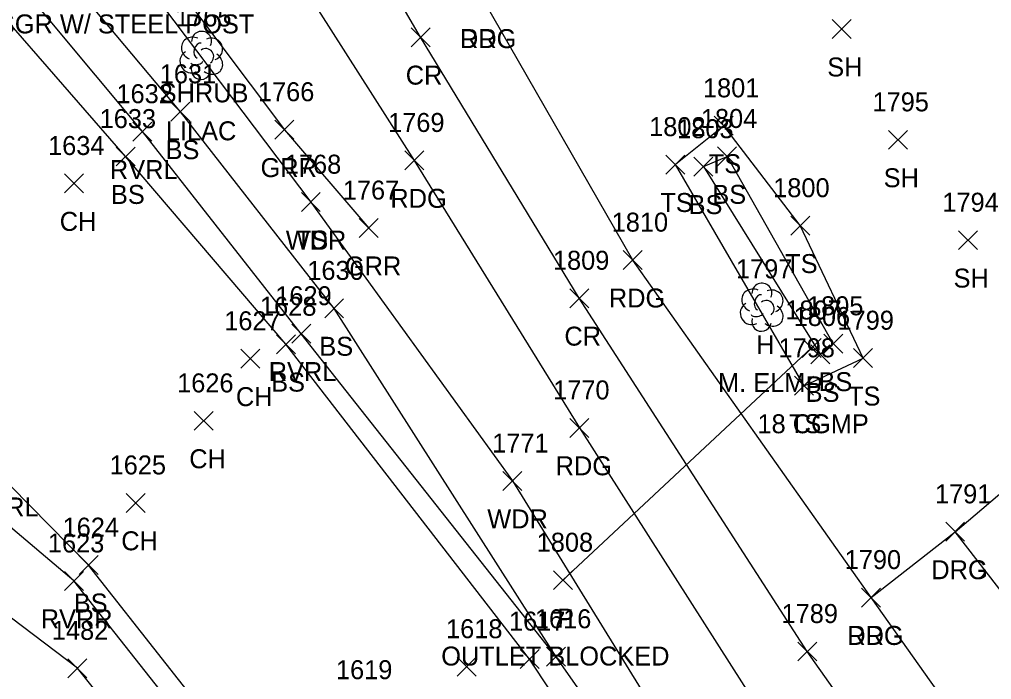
# Model space of a CAD drawing. Extents: x 1653908 to 1654393, y 539913 to 544256.
# Drawn here: x 1654097.1 to 1654199.7, y 541548 to 541617.6 of the extents above; entities that cross this region are included whole.
import ezdxf

# ---------------------------------------------------------------- set-up
doc = ezdxf.new("R2010")
doc.units = 0
for name, color, linetype in [('C_A', 7, 'Continuous'), ('D_A', 7, 'Continuous'), ('D_C', 7, 'Continuous'), ('D_I', 7, 'Continuous'), ('D_TIC', 7, 'Continuous'), ('DCP', 7, 'Continuous'), ('L_A', 7, 'Continuous'), ('L_C', 7, 'Continuous'), ('L_I', 7, 'Continuous'), ('L_TIC', 7, 'Continuous'), ('LAWA', 7, 'Continuous'), ('LAWE', 7, 'Continuous'), ('LELB', 7, 'Continuous'), ('LSH', 7, 'Continuous'), ('LTD', 7, 'Continuous'), ('P_A', 7, 'Continuous'), ('P_I', 7, 'Continuous'), ('P_TIC', 7, 'Continuous'), ('PEU', 7, 'Continuous'), ('PRC', 7, 'Continuous'), ('R_A', 7, 'Continuous'), ('R_C', 7, 'Continuous'), ('R_I', 7, 'Continuous'), ('R_TIC', 7, 'Continuous'), ('RDG', 7, 'Continuous'), ('RDP', 7, 'Continuous'), ('RGR', 7, 'Continuous')]:
    doc.layers.add(name, color=color, linetype=linetype)

msp = doc.modelspace()

# ---------------------------------------------------------------- linework, layer by layer
at = {"layer": 'D_TIC'}
for points in [[(1654179.68, 541582), (1654181.68, 541584)], [(1654181.68, 541582), (1654179.68, 541584)], [(1654153.46, 541557.51), (1654155.46, 541559.51)], [(1654155.46, 541557.51), (1654153.46, 541559.51)]]:
    msp.add_lwpolyline(points, dxfattribs=at)
at = {"layer": 'DCP'}
msp.add_lwpolyline([(1654180.68, 541583), (1654154.46, 541558.51)], dxfattribs=at)
at = {"layer": 'L_TIC'}
for points in [[(1654182.84, 541615.62), (1654184.84, 541617.62)], [(1654184.84, 541615.62), (1654182.84, 541617.62)], [(1654113.11, 541606.9), (1654115.11, 541608.9)], [(1654115.11, 541606.9), (1654113.11, 541608.9)], [(1654170.42, 541605.42), (1654172.42, 541607.42)], [(1654172.42, 541605.42), (1654170.42, 541607.42)], [(1654109.11, 541604.8), (1654111.11, 541606.8)], [(1654111.11, 541604.8), (1654109.11, 541606.8)], [(1654188.8, 541603.94), (1654190.8, 541605.94)], [(1654190.8, 541603.94), (1654188.8, 541605.94)], [(1654107.34, 541602.18), (1654109.34, 541604.18)], [(1654109.34, 541602.18), (1654107.34, 541604.18)], [(1654170.77, 541602.19), (1654172.77, 541604.19)], [(1654172.77, 541602.19), (1654170.77, 541604.19)], [(1654165.32, 541601.33), (1654167.32, 541603.33)], [(1654167.32, 541601.33), (1654165.32, 541603.33)], [(1654165.32, 541601.33), (1654167.32, 541603.33)], [(1654167.32, 541601.33), (1654165.32, 541603.33)], [(1654168.27, 541601.11), (1654170.27, 541603.11)], [(1654170.27, 541601.11), (1654168.27, 541603.11)], [(1654168.27, 541601.11), (1654170.27, 541603.11)], [(1654170.27, 541601.11), (1654168.27, 541603.11)], [(1654101.9, 541599.34), (1654103.9, 541601.34)], [(1654103.9, 541599.34), (1654101.9, 541601.34)], [(1654126.87, 541597.37), (1654128.87, 541599.37)], [(1654128.87, 541597.37), (1654126.87, 541599.37)], [(1654126.87, 541597.37), (1654128.87, 541599.37)], [(1654128.87, 541597.37), (1654126.87, 541599.37)], [(1654178.49, 541594.89), (1654180.49, 541596.89)], [(1654180.49, 541594.89), (1654178.49, 541596.89)], [(1654196.16, 541593.36), (1654198.16, 541595.36)], [(1654198.16, 541593.36), (1654196.16, 541595.36)], [(1654129.33, 541586.17), (1654131.33, 541588.17)], [(1654131.33, 541586.17), (1654129.33, 541588.17)], [(1654125.86, 541583.5), (1654127.86, 541585.5)], [(1654127.86, 541583.5), (1654125.86, 541585.5)], [(1654124.25, 541582.39), (1654126.25, 541584.39)], [(1654126.25, 541582.39), (1654124.25, 541584.39)], [(1654181.96, 541582.44), (1654183.96, 541584.44)], [(1654183.96, 541582.44), (1654181.96, 541584.44)], [(1654180.61, 541581.31), (1654182.61, 541583.31)], [(1654182.61, 541581.31), (1654180.61, 541583.31)], [(1654180.61, 541581.31), (1654182.61, 541583.31)], [(1654182.61, 541581.31), (1654180.61, 541583.31)], [(1654120.48, 541580.86), (1654122.48, 541582.86)], [(1654122.48, 541580.86), (1654120.48, 541582.86)], [(1654185.11, 541580.92), (1654187.11, 541582.92)], [(1654187.11, 541580.92), (1654185.11, 541582.92)], [(1654178.88, 541578.01), (1654180.88, 541580.01)], [(1654180.88, 541578.01), (1654178.88, 541580.01)], [(1654178.88, 541578.01), (1654180.88, 541580.01)], [(1654180.88, 541578.01), (1654178.88, 541580.01)], [(1654115.57, 541574.31), (1654117.57, 541576.31)], [(1654117.57, 541574.31), (1654115.57, 541576.31)], [(1654148.12, 541567.97), (1654150.12, 541569.97)], [(1654150.12, 541567.97), (1654148.12, 541569.97)], [(1654108.39, 541565.66), (1654110.39, 541567.66)], [(1654110.39, 541565.66), (1654108.39, 541567.66)], [(1654103.43, 541559.1), (1654105.43, 541561.1)], [(1654105.43, 541559.1), (1654103.43, 541561.1)], [(1654101.88, 541557.43), (1654103.88, 541559.43)], [(1654103.88, 541557.43), (1654101.88, 541559.43)], [(1654149.94, 541549.19), (1654151.94, 541551.19)], [(1654151.94, 541549.19), (1654149.94, 541551.19)], [(1654152.73, 541549.44), (1654154.73, 541551.44)], [(1654154.73, 541549.44), (1654152.73, 541551.44)], [(1654152.73, 541549.44), (1654154.73, 541551.44)], [(1654154.73, 541549.44), (1654152.73, 541551.44)], [(1654102.25, 541548.22), (1654104.25, 541550.22)], [(1654104.25, 541548.22), (1654102.25, 541550.22)], [(1654143.3, 541548.39), (1654145.3, 541550.39)], [(1654145.3, 541548.39), (1654143.3, 541550.39)]]:
    msp.add_lwpolyline(points, dxfattribs=at)
at = {"layer": 'LAWA'}
msp.add_lwpolyline([(1654127.87, 541598.37), (1654149.12, 541568.97), (1654169.48, 541535.98), (1654185.51, 541509.19), (1654208.26, 541476.29)], dxfattribs=at)
at = {"layer": 'LAWE'}
for points in [[(1654199.26, 541471.36), (1654181.86, 541503.28), (1654178.82, 541509.62), (1654164.46, 541535.09), (1654153.73, 541550.44), (1654126.86, 541584.5), (1654110.11, 541605.8), (1654090.45, 541629.39), (1654082.44, 541647.34), (1654069.57, 541661.67), (1654051.08, 541684.15), (1654038.47, 541696.15), (1654026.73, 541704.45), (1654010.8, 541724.45), (1653979.68, 541745.5), (1653961.84, 541751.35), (1653943.48, 541769.15)], [(1654165.75, 541453.3), (1654145.37, 541485.64), (1654128.33, 541517.88), (1654118.98, 541538.06), (1654102.88, 541558.43), (1654087.64, 541571.29), (1654080.69, 541574.23), (1654068.7, 541590.65), (1654047.98, 541616.51), (1654043.58, 541623.07), (1654031.27, 541642.94), (1654001.65, 541675.05), (1653981.82, 541702.27), (1653972.91, 541712.11), (1653946.21, 541722.65), (1653929.33, 541730.47)]]:
    msp.add_lwpolyline(points, dxfattribs=at)
at = {"layer": 'LELB'}
for points in [[(1654082.8, 541659.57), (1654085.49, 541655.52), (1654087.66, 541650.15), (1654089.71, 541642), (1654097.55, 541632.45), (1654102.9, 541633.54), (1654108.64, 541623.86), (1654127.87, 541598.37)], [(1654196.93, 541471.45), (1654180.81, 541502.22), (1654177.72, 541510.01), (1654161.8, 541533.8), (1654150.94, 541550.19), (1654125.25, 541583.39), (1654108.34, 541603.18), (1654088.22, 541626.26), (1654081.33, 541637.75)], [(1654153.73, 541550.44), (1654130.33, 541587.17), (1654114.11, 541607.9), (1654099.82, 541624.98)], [(1654179.88, 541579.01), (1654186.11, 541581.92), (1654179.49, 541595.89), (1654171.42, 541606.42), (1654166.32, 541602.33)], [(1654169.27, 541602.11), (1654171.77, 541603.19), (1654182.96, 541583.44), (1654181.61, 541582.31)], [(1654179.88, 541579.01), (1654166.32, 541602.33)], [(1654169.27, 541602.11), (1654181.61, 541582.31)], [(1654167.93, 541456.34), (1654149.35, 541485.29), (1654131.62, 541518.7), (1654120.79, 541539.28), (1654104.43, 541560.1), (1654087.96, 541576.78)], [(1654111.1, 541539.43), (1654103.25, 541549.22), (1654091.64, 541558.03), (1654091.64, 541546.03), (1654092.66, 541531.19), (1654087.6, 541525.06), (1654080.77, 541525.51), (1654079.92, 541532.39), (1654080.83, 541544.02)]]:
    msp.add_lwpolyline(points, dxfattribs=at)
at = {"layer": 'LSH'}
msp.add_line((1654116.3, 541613.89), (1654116.3, 541613.89), dxfattribs=at)
msp.add_line((1654116.3, 541613.89), (1654116.3, 541613.89), dxfattribs=at)
msp.add_arc((1654116.35, 541615.33), 1.05, 335.5272, 180.9563, dxfattribs=at)
for centre, major_axis, ratio, start_param, end_param in [((1654115.51, 541614.56), (1.21, -0.51), 0.895232, 1.570796, 4.712389), ((1654116.09, 541614.35), (-0.208, -0.792), 0.645439, 3.141593, 6.283185), ((1654117.34, 541614.48), (-1.14, -0.48), 0.949671, 1.570796, 4.712389), ((1654115.22, 541613.18), (0.58, -1.04), 0.959034, 3.141593, 6.283185), ((1654116.8, 541613.73), (-0.5, 0.667), 0.989748, 3.141593, 6.283185), ((1654115.84, 541613.14), (-0.625, -0.083), 0.423636, 0, 3.141593), ((1654117.3, 541613.06), (-1.09, 0.79), 0.841452, 1.570796, 4.712389), ((1654116.3, 541612.39), (0.26, 1.06), 0.942809, 1.570796, 4.712389)]:
    msp.add_ellipse(centre, major_axis=major_axis, ratio=ratio, start_param=start_param, end_param=end_param, dxfattribs=at)
at = {"layer": 'LTD'}
msp.add_line((1654175.4, 541587.34), (1654175.4, 541587.34), dxfattribs=at)
msp.add_line((1654175.4, 541587.34), (1654175.4, 541587.34), dxfattribs=at)
msp.add_arc((1654175.44, 541588.77), 1.05, 335.5272, 180.9563, dxfattribs=at)
for centre, major_axis, ratio, start_param, end_param in [((1654174.6, 541588), (1.21, -0.51), 0.895232, 1.570796, 4.712389), ((1654175.19, 541587.8), (-0.208, -0.792), 0.645439, 3.141593, 6.283185), ((1654176.44, 541587.92), (-1.14, -0.48), 0.949671, 1.570796, 4.712389), ((1654174.31, 541586.63), (0.58, -1.04), 0.959034, 3.141593, 6.283185), ((1654175.9, 541587.17), (-0.5, 0.667), 0.989748, 3.141593, 6.283185), ((1654176.4, 541586.5), (-1.09, 0.79), 0.841452, 1.570796, 4.712389), ((1654174.94, 541586.59), (-0.625, -0.083), 0.423636, 0, 3.141593), ((1654175.4, 541585.84), (0.26, 1.06), 0.942809, 1.570796, 4.712389)]:
    msp.add_ellipse(centre, major_axis=major_axis, ratio=ratio, start_param=start_param, end_param=end_param, dxfattribs=at)
at = {"layer": 'P_TIC'}
for points in [[(1654138.45, 541614.76), (1654140.45, 541616.76)], [(1654140.45, 541614.76), (1654138.45, 541616.76)], [(1654137.77, 541601.77), (1654139.77, 541603.77)], [(1654139.77, 541601.77), (1654137.77, 541603.77)], [(1654160.81, 541591.26), (1654162.81, 541593.26)], [(1654162.81, 541591.26), (1654160.81, 541593.26)], [(1654155.18, 541587.24), (1654157.18, 541589.24)], [(1654157.18, 541587.24), (1654155.18, 541589.24)], [(1654155.2, 541573.57), (1654157.2, 541575.57)], [(1654157.2, 541573.57), (1654155.2, 541575.57)], [(1654185.95, 541555.68), (1654187.95, 541557.68)], [(1654187.95, 541555.68), (1654185.95, 541557.68)], [(1654179.22, 541549.99), (1654181.22, 541551.99)], [(1654181.22, 541549.99), (1654179.22, 541551.99)]]:
    msp.add_lwpolyline(points, dxfattribs=at)
at = {"layer": 'PEU'}
for points in [[(1654230.6, 541492.16), (1654211.67, 541521.82), (1654186.95, 541556.68), (1654161.81, 541592.26), (1654146.11, 541619.61), (1654138.24, 541633.78), (1654124.52, 541663.98), (1654122.03, 541667.7)], [(1654099.96, 541660.14), (1654114.2, 541641.31), (1654138.77, 541602.77), (1654156.2, 541574.57), (1654177.92, 541540.51), (1654193.38, 541516.71), (1654218.32, 541481.56)]]:
    msp.add_lwpolyline(points, dxfattribs=at)
at = {"layer": 'PRC'}
msp.add_lwpolyline([(1654225.01, 541487.06), (1654204.16, 541517.09), (1654180.22, 541550.99), (1654156.18, 541588.24), (1654139.45, 541615.76), (1654117.3, 541653.68), (1654111.9, 541663.59), (1654098.63, 541686.77), (1654084.43, 541705.04)], dxfattribs=at)
at = {"layer": 'R_TIC'}
for points in [[(1654124.09, 541605.01), (1654126.09, 541607.01)], [(1654126.09, 541605.01), (1654124.09, 541607.01)], [(1654132.98, 541594.64), (1654134.98, 541596.64)], [(1654134.98, 541594.64), (1654132.98, 541596.64)], [(1654194.82, 541562.61), (1654196.82, 541564.61)], [(1654196.82, 541562.61), (1654194.82, 541564.61)], [(1654194.82, 541562.61), (1654196.82, 541564.61)], [(1654196.82, 541562.61), (1654194.82, 541564.61)], [(1654185.95, 541555.68), (1654187.95, 541557.68)], [(1654187.95, 541555.68), (1654185.95, 541557.68)]]:
    msp.add_lwpolyline(points, dxfattribs=at)
at = {"layer": 'RDG'}
msp.add_lwpolyline([(1654186.95, 541556.68), (1654195.82, 541563.61)], dxfattribs=at)
at = {"layer": 'RDP'}
msp.add_lwpolyline([(1654244.38, 541502.13), (1654222.95, 541528.61), (1654195.82, 541563.61), (1654203.1, 541569.78)], dxfattribs=at)
at = {"layer": 'RGR'}
msp.add_lwpolyline([(1654110.7, 541625.16), (1654125.09, 541606.01), (1654133.98, 541595.64)], dxfattribs=at)

# ---------------------------------------------------------------- texts
at = {"layer": 'C_A'}
msp.add_text('HVCTRL', height=2, dxfattribs=at).set_placement((1654088.46, 541565.23))
at = {"layer": 'D_A'}
for p in [(1654180.06, 541578), (1654153.84, 541553.51)]:
    msp.add_text('P', height=2, dxfattribs=at).set_placement(p)
at = {"layer": 'D_C'}
for s, p in [('18 CGMP', (1654174.97, 541574)), ('OUTLET BLOCKED', (1654141.62, 541549.51))]:
    msp.add_text(s, height=2, dxfattribs=at).set_placement(p)
at = {"layer": 'D_I'}
for s, p in [('1807', (1654177.91, 541586)), ('1808', (1654151.69, 541561.51))]:
    msp.add_text(s, height=2, dxfattribs=at).set_placement(p)
at = {"layer": 'L_A'}
for s, p in [('SH', (1654182.33, 541611.62)), ('SHRUB', (1654111.93, 541608.89)), ('BS', (1654112.55, 541602.9)), ('RVRL', (1654106.68, 541600.8)), ('TS', (1654169.83, 541601.42)), ('SH', (1654188.28, 541599.94)), ('BS', (1654106.79, 541598.18)), ('BS', (1654170.21, 541598.19)), ('TS', (1654164.73, 541597.33)), ('TS', (1654164.73, 541597.33)), ('BS', (1654167.71, 541597.11)), ('BS', (1654167.71, 541597.11)), ('CH', (1654101.39, 541595.34)), ('WDR', (1654125.23, 541593.37)), ('TS', (1654126.28, 541593.37)), ('TS', (1654177.9, 541590.89)), ('SH', (1654195.65, 541589.36)), ('H', (1654174.83, 541582.34)), ('BS', (1654128.77, 541582.17)), ('RVRL', (1654123.43, 541579.5)), ('BS', (1654123.69, 541578.39)), ('BS', (1654181.4, 541578.44)), ('BS', (1654180.05, 541577.31)), ('BS', (1654180.05, 541577.31)), ('CH', (1654119.97, 541576.86)), ('TS', (1654184.52, 541576.92)), ('TS', (1654178.29, 541574.01)), ('TS', (1654178.29, 541574.01)), ('CH', (1654115.05, 541570.31)), ('WDR', (1654146.48, 541563.97)), ('CH', (1654107.88, 541561.66)), ('BS', (1654102.87, 541555.1)), ('RVRR', (1654099.39, 541553.43))]:
    msp.add_text(s, height=2, dxfattribs=at).set_placement(p)
at = {"layer": 'L_C'}
for s, p in [('LILAC', (1654112.58, 541604.89)), ('M. ELM', (1654170.81, 541578.34))]:
    msp.add_text(s, height=2, dxfattribs=at).set_placement(p)
at = {"layer": 'L_I'}
for s, p in [('1765', (1654113.56, 541616.89)), ('1631', (1654111.94, 541610.9)), ('1801', (1654169.22, 541609.42)), ('1632', (1654107.37, 541608.8)), ('1795', (1654187.1, 541607.94)), ('1633', (1654105.6, 541606.18)), ('1804', (1654169, 541606.19)), ('1802', (1654163.55, 541605.33)), ('1802', (1654163.55, 541605.33)), ('1803', (1654166.5, 541605.11)), ('1803', (1654166.5, 541605.11)), ('1634', (1654100.16, 541603.34)), ('1768', (1654125.13, 541601.37)), ('1768', (1654125.13, 541601.37)), ('1800', (1654176.63, 541598.89)), ('1794', (1654194.47, 541597.36)), ('1630', (1654127.5, 541590.17)), ('1797', (1654172.7, 541590.34)), ('1629', (1654124.12, 541587.5)), ('1628', (1654122.51, 541586.39)), ('1805', (1654180.19, 541586.44)), ('1627', (1654118.74, 541584.86)), ('1806', (1654178.79, 541585.31)), ('1806', (1654178.79, 541585.31)), ('1799', (1654183.41, 541584.92)), ('1798', (1654177.19, 541582.01)), ('1798', (1654177.19, 541582.01)), ('1626', (1654113.77, 541578.31)), ('1771', (1654146.99, 541571.97)), ('1625', (1654106.65, 541569.66)), ('1624', (1654101.69, 541563.1)), ('1623', (1654100.14, 541561.43)), ('1617', (1654148.77, 541553.19)), ('1616', (1654151.5, 541553.44)), ('1616', (1654151.5, 541553.44)), ('1482', (1654100.56, 541552.22)), ('1618', (1654142.13, 541552.39)), ('1619', (1654130.52, 541548.07))]:
    msp.add_text(s, height=2, dxfattribs=at).set_placement(p)
at = {"layer": 'P_A'}
for s, p in [('RDG', (1654143.6, 541614.61)), ('CR', (1654137.88, 541610.76)), ('RDG', (1654136.26, 541597.77)), ('RDG', (1654159.3, 541587.26)), ('CR', (1654154.61, 541583.24)), ('RDG', (1654153.69, 541569.57)), ('RDG', (1654184.44, 541551.68))]:
    msp.add_text(s, height=2, dxfattribs=at).set_placement(p)
at = {"layer": 'P_I'}
for s, p in [('1769', (1654136.02, 541605.77)), ('1810', (1654159.6, 541595.26)), ('1809', (1654153.4, 541591.24)), ('1770', (1654153.42, 541577.57)), ('1790', (1654184.17, 541559.68)), ('1789', (1654177.51, 541553.99))]:
    msp.add_text(s, height=2, dxfattribs=at).set_placement(p)
at = {"layer": 'R_A'}
for s, p in [('DRG', (1654143.6, 541614.61)), ('GRR', (1654122.57, 541601.01)), ('GRR', (1654131.47, 541590.64)), ('DRG', (1654193.31, 541558.61)), ('DRC', (1654193.31, 541558.61)), ('DRG', (1654184.44, 541551.68))]:
    msp.add_text(s, height=2, dxfattribs=at).set_placement(p)
at = {"layer": 'R_C'}
msp.add_text('SGR W/ STEEL POST', height=2, dxfattribs=at).set_placement((1654094.87, 541616.16))
at = {"layer": 'R_I'}
for s, p in [('1766', (1654122.29, 541609.01)), ('1767', (1654131.24, 541598.64)), ('1791', (1654193.69, 541566.61)), ('1791', (1654193.69, 541566.61)), ('1790', (1654184.17, 541559.68))]:
    msp.add_text(s, height=2, dxfattribs=at).set_placement(p)

doc.saveas('drawing.dxf')
